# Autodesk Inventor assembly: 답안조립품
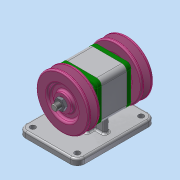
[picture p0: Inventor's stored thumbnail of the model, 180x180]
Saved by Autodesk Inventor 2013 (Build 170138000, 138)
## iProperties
Created: 2020-11
Part Number: 답안조립품
Document SubType Name: Assembly
Designer: user
Author: user
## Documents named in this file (10)
- C:\Users\user\Desktop\701106V1035\답안조립품.iam
- C:\Users\user\Desktop\701106V1035\본체.ipt
- C:\Users\user\Desktop\701106V1035\볼트 M4.ipt
- C:\Users\user\Desktop\701106V1035\축.ipt
- C:\Users\user\Desktop\701106V1035\V-벨트풀리.ipt
- C:\Users\user\Desktop\701106V1035\너트 M10x1.ipt
- C:\Users\user\Desktop\701106V1035\베어링 6004.ipt
- C:\Users\user\Desktop\701106V1035\오일 실 17 30 5.ipt
- C:\Users\user\Desktop\701106V1035\커버.ipt
- C:\Users\user\Desktop\701106V1035\키 5 x 5 x 12.ipt
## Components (2 placed, 1 different names)
1. V-벨트풀리:1
2. V-벨트풀리:2
## Component patterns: 구성요소 패턴 1:2 (2 elements), 구성요소 패턴 3:2 (2 elements)
